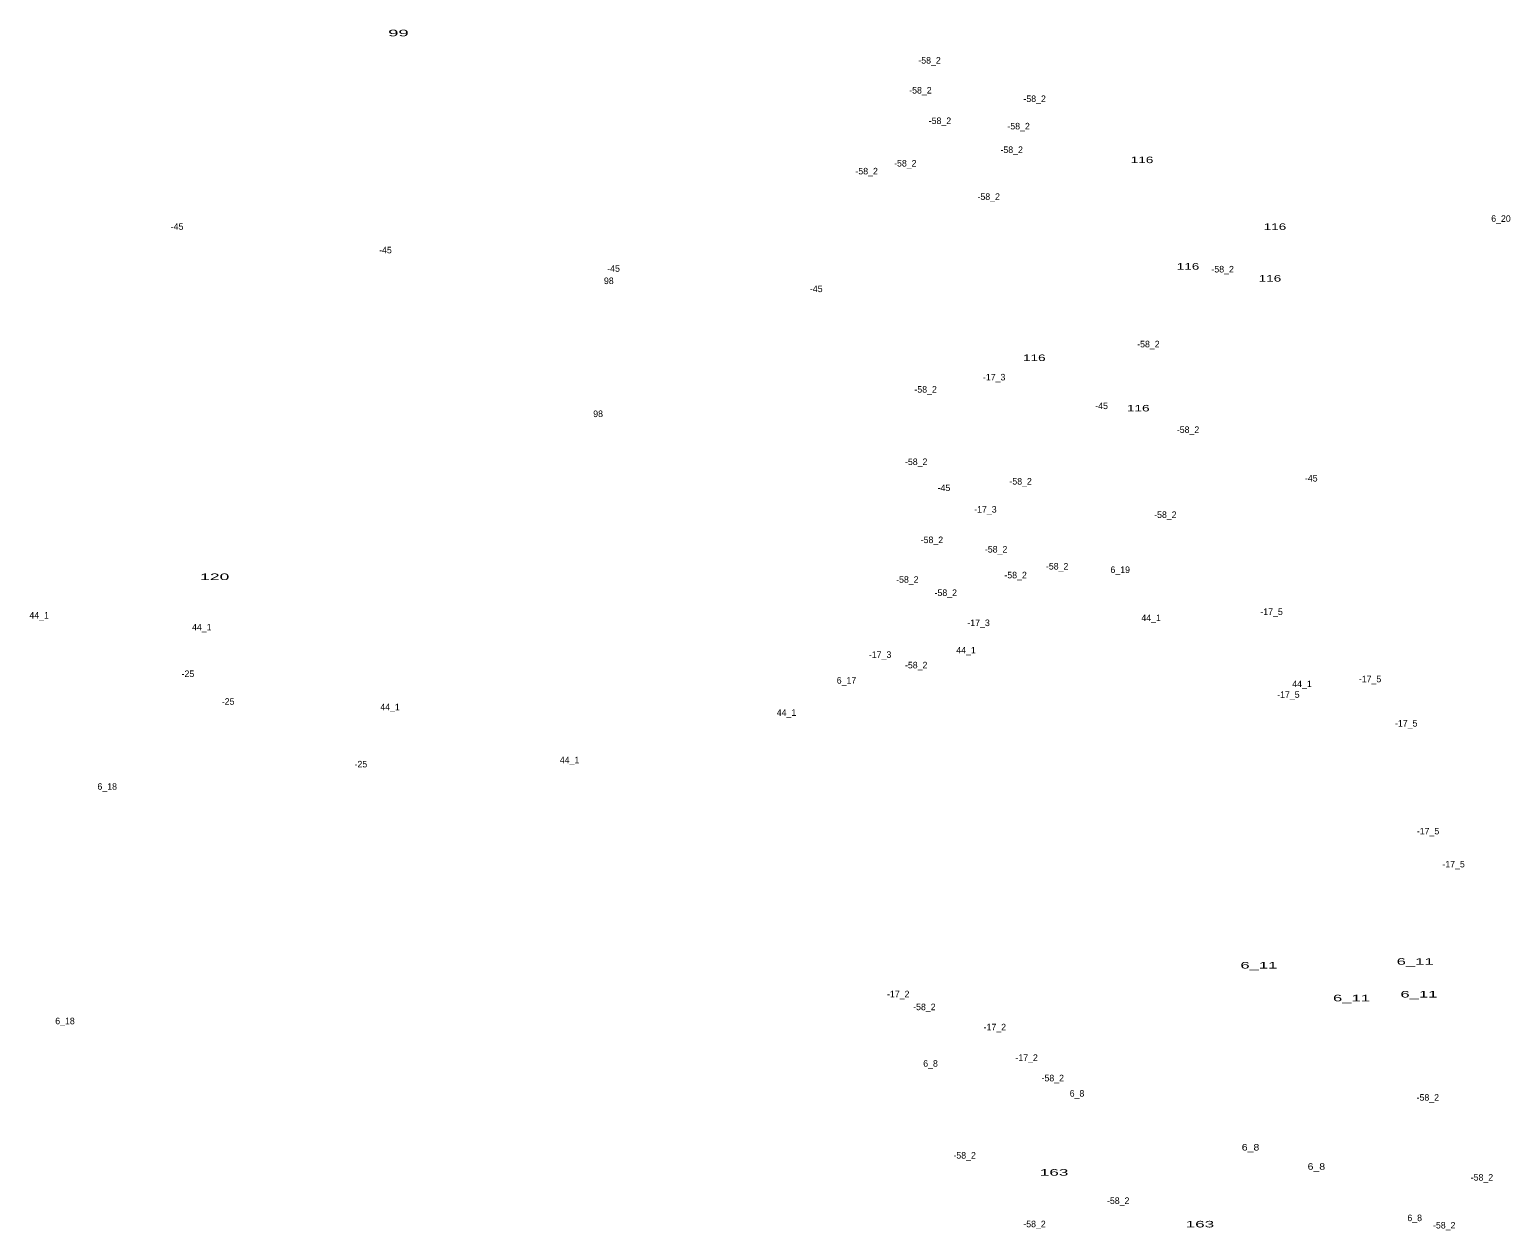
# Model space of a CAD drawing. Extents: x -659624 to -656248, y -1006345 to -1003555.
# Drawn here: x -658650 to -657747, y -1004288 to -1003555 of the extents above; entities that cross this region are included whole.
import ezdxf
from ezdxf.enums import TextEntityAlignment as Align

# ---------------------------------------------------------------- set-up
doc = ezdxf.new("R2010")
doc.units = 0
doc.header["$LTSCALE"] = 1.6
doc.layers.add('24', color=7, linetype='Continuous')

msp = doc.modelspace()

# ---------------------------------------------------------------- texts
at = {"layer": '24'}
for s, width, p in [('99', 2.1, (-658425.281, -1003559.37)), ('116', 1.55, (-657971.519, -1003636.8)), ('116', 1.55, (-657890.399, -1003677.57)), ('116', 1.55, (-657943.459, -1003701.8)), ('116', 1.55, (-657893.469, -1003709.11)), ('116', 1.55, (-658037.269, -1003757.57)), ('116', 1.55, (-657973.829, -1003788.34)), ('120', 2, (-658537.394, -1003891.23)), ('6_11', 1.9, (-657900.2, -1004128.31)), ('6_11', 1.9, (-657804.85, -1004126)), ('6_11', 1.9, (-657843.68, -1004148.31)), ('6_11', 1.9, (-657802.54, -1004146)), ('6_8', 1.2, (-657905.299, -1004239.38)), ('163', 1.95, (-658025.173, -1004254.73)), ('6_8', 1.2, (-657865.13, -1004251.12)), ('163', 1.95, (-657936.173, -1004286.32))]:
    msp.add_text(s, height=4, dxfattribs=dict(at, width=width)).set_placement(p, align=Align.CENTER)
for s, p in [('-58_2', (-658101.172, -1003576.07)), ('-58_2', (-658106.742, -1003594.32)), ('-58_2', (-658037.042, -1003599.51)), ('-58_2', (-658094.832, -1003612.95)), ('-58_2', (-658046.832, -1003616.22)), ('-58_2', (-658051.062, -1003630.62)), ('-58_2', (-658139.572, -1003643.68)), ('-58_2', (-658115.962, -1003638.88)), ('-58_2', (-658065.072, -1003659.24)), ('-45', (-658560.369, -1003677.5)), ('6_20', (-657752.474, -1003672.62)), ('-45', (-658433.199, -1003691.85)), ('-45', (-658293.999, -1003703.1)), ('-58_2', (-657922.322, -1003703.51)), ('98', (-658296.893, -1003710.61)), ('-45', (-658170.309, -1003715.51)), ('-58_2', (-657967.632, -1003749.22)), ('-17_3', (-658061.752, -1003769.41)), ('-58_2', (-658103.572, -1003776.88)), ('-45', (-657996.199, -1003786.9)), ('98', (-658303.433, -1003791.77)), ('-58_2', (-657943.442, -1003801.47)), ('-58_2', (-658109.332, -1003821.06)), ('-58_2', (-658045.592, -1003832.96)), ('-45', (-657868.249, -1003831.12)), ('-45', (-658092.369, -1003836.92)), ('-17_3', (-658067.082, -1003850.07)), ('-58_2', (-657957.262, -1003853.33)), ('-58_2', (-658099.732, -1003868.69)), ('-58_2', (-658060.562, -1003874.45)), ('-58_2', (-658023.312, -1003884.82)), ('6_19', (-657984.82, -1003886.93)), ('-58_2', (-658114.712, -1003892.89)), ('-58_2', (-658048.662, -1003890.2)), ('-58_2', (-658091.282, -1003900.96)), ('44_1', (-658644.518, -1003914.74)), ('44_1', (-657965.948, -1003916.26)), ('-17_5', (-657892.462, -1003912.54)), ('44_1', (-658545.248, -1003921.97)), ('-17_3', (-658071.262, -1003919.33)), ('-17_3', (-658131.362, -1003938.73)), ('44_1', (-658078.918, -1003936.05)), ('-25', (-658553.745, -1003950.41)), ('-58_2', (-658109.332, -1003945.14)), ('6_17', (-658151.85, -1003954.43)), ('44_1', (-657873.898, -1003956.6)), ('-17_5', (-657832.362, -1003953.63)), ('-25', (-658529.215, -1003967.34)), ('44_1', (-658430.378, -1003970.68)), ('-17_5', (-657882.192, -1003963.14)), ('44_1', (-658188.458, -1003974.1)), ('-17_5', (-657810.302, -1003980.65)), ('-25', (-658448.195, -1004005.58)), ('44_1', (-658320.828, -1004003.02)), ('6_18', (-658602.994, -1004019.22)), ('-17_5', (-657796.982, -1004046.45)), ('-17_5', (-657781.392, -1004066.61)), ('-17_2', (-658120.292, -1004145.89)), ('-58_2', (-658104.322, -1004153.73)), ('6_18', (-658628.754, -1004162.3)), ('-17_2', (-658061.332, -1004166.05)), ('-17_2', (-658041.932, -1004184.7)), ('6_8', (-658100.581, -1004188.23)), ('-58_2', (-658025.982, -1004197.14)), ('6_8', (-658011.191, -1004206.51)), ('-58_2', (-657797.112, -1004208.98)), ('-58_2', (-658079.752, -1004244.32)), ('-58_2', (-657764.082, -1004257.77)), ('-58_2', (-657986.052, -1004271.98)), ('-58_2', (-658037.122, -1004286.19)), ('6_8', (-657805.121, -1004282.47)), ('-58_2', (-657787.122, -1004286.96))]:
    msp.add_text(s, height=4, dxfattribs=at).set_placement(p, align=Align.CENTER)

doc.saveas('drawing.dxf')
